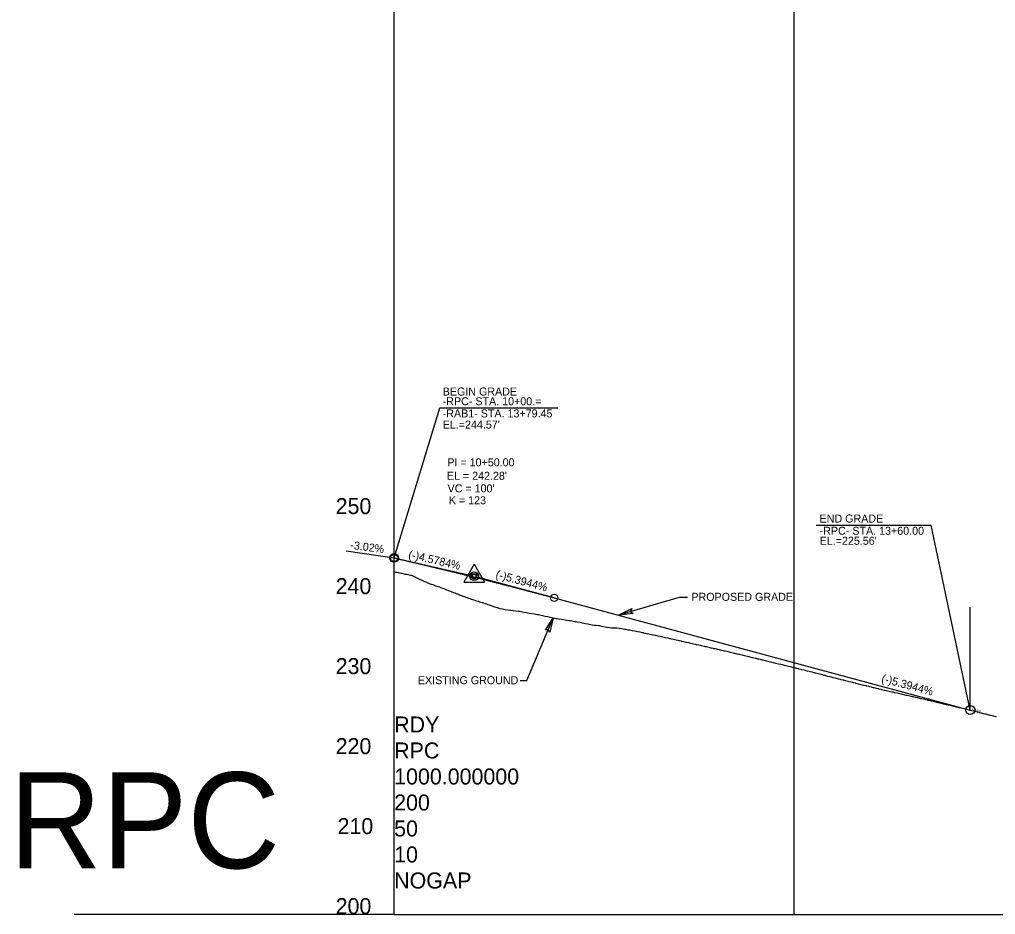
# Model space of a CAD drawing. Extents: x 2115752 to 2121174, y 562881 to 567245.
# Drawn here: x 2116462 to 2117072, y 563768 to 564327 of the extents above; entities that cross this region are included whole.
import ezdxf

# ---------------------------------------------------------------- set-up
doc = ezdxf.new("R2010")
doc.units = 0
for name, color, linetype in [('Exist Profile Cell', 7, 'Continuous'), ('Exist Vertical Profile Ground Line', 7, 'Continuous'), ('Exist Vertical Profile Vertical Axis Label', 7, 'Continuous'), ('Prop PFL VPI Symbol CELL', 7, 'Continuous'), ('Prop Terminator CELL', 7, 'Continuous'), ('Prop Vertical Profile Curve Label', 7, 'Continuous'), ('Prop Vertical Profile Grade', 7, 'Continuous'), ('Prop Vertical Profile Grade Label', 7, 'Continuous'), ('Prop VPI Label', 7, 'Continuous'), ('Scratch_Level_1', 7, 'Continuous')]:
    doc.layers.add(name, color=color, linetype=linetype)

msp = doc.modelspace()

# ---------------------------------------------------------------- linework, layer by layer
at = {"layer": 'Exist Profile Cell'}
for q in [(2116696.3, 564017.63), (2117393.32, 563767.63), (2116696.3, 563767.63)]:
    msp.add_line((2116696.3, 563767.63), q, dxfattribs=at)
at = {"layer": 'Exist Vertical Profile Ground Line'}
msp.add_lwpolyline([(2116696.3, 563981.85), (2116697.16, 563981.66), (2116698.02, 563981.48), (2116698.89, 563981.29), (2116699.74, 563981.13), (2116700.67, 563980.95), (2116701.01, 563980.87), (2116701.69, 563980.75), (2116702.32, 563980.61), (2116703.24, 563980.42), (2116704.13, 563980.28), (2116704.9, 563980.14), (2116705.76, 563979.97), (2116706.62, 563979.81), (2116706.94, 563979.75), (2116707.48, 563979.52), (2116708.34, 563979.15), (2116709.25, 563978.76), (2116710.06, 563978.34), (2116710.92, 563977.89), (2116711.78, 563977.44), (2116712.64, 563977), (2116713.11, 563976.76), (2116713.5, 563976.58), (2116714.36, 563976.2), (2116715.22, 563975.82), (2116716.08, 563975.44), (2116716.94, 563975.06), (2116717.8, 563974.69), (2116718.16, 563974.53), (2116718.67, 563974.37), (2116719.53, 563974.09), (2116720.39, 563973.8), (2116721.25, 563973.44), (2116722.11, 563973.08), (2116722.97, 563972.76), (2116723.83, 563972.57), (2116724.71, 563972.37), (2116725.55, 563972.02), (2116726.41, 563971.66), (2116727.27, 563971.31), (2116728.13, 563970.96), (2116728.99, 563970.62), (2116729.85, 563970.28), (2116730.71, 563969.94), (2116731.57, 563969.61), (2116732.43, 563969.28), (2116733.29, 563968.96), (2116734.15, 563968.64), (2116735.01, 563968.32), (2116735.53, 563968.13), (2116735.87, 563967.96), (2116736.73, 563967.55), (2116737.59, 563967.23), (2116738.45, 563966.92), (2116739.31, 563966.6), (2116740.17, 563966.29), (2116741.03, 563965.99), (2116741.89, 563965.68), (2116742.75, 563965.38), (2116743.61, 563965.09), (2116744.47, 563964.79), (2116745.33, 563964.5), (2116746.19, 563964.22), (2116747.05, 563963.93), (2116747.91, 563963.65), (2116748.77, 563963.38), (2116749.73, 563963.07), (2116750.49, 563962.87), (2116751.35, 563962.66), (2116751.78, 563962.55), (2116752.21, 563962.39), (2116753.07, 563962.07), (2116753.93, 563961.75), (2116754.79, 563961.44), (2116755.65, 563961.14), (2116757.32, 563960.56), (2116758.98, 563959.98), (2116760.65, 563959.41), (2116762.39, 563958.83), (2116763.99, 563958.58), (2116765.66, 563958.34), (2116767.33, 563958.1), (2116768.51, 563957.93), (2116768.99, 563957.86), (2116770.66, 563957.63), (2116772.33, 563957.4), (2116774, 563957.18), (2116774.62, 563957.11), (2116775.67, 563956.91), (2116777.34, 563956.61), (2116779, 563956.31), (2116780.67, 563956.03), (2116782.34, 563955.74), (2116784.01, 563955.47), (2116785.68, 563955.2), (2116786.56, 563955.05), (2116787.35, 563954.88), (2116789.01, 563954.51), (2116790.68, 563954.15), (2116792.35, 563953.79), (2116794.02, 563953.43), (2116795.69, 563953.07), (2116797.36, 563952.72), (2116798.25, 563952.53), (2116799.02, 563952.42), (2116800.69, 563952.18), (2116802.36, 563951.92), (2116804.03, 563951.66), (2116805.7, 563951.4), (2116806.22, 563951.32), (2116807.37, 563951.12), (2116809.03, 563950.83), (2116809.73, 563950.71), (2116810.7, 563950.54), (2116812.37, 563950.25), (2116814.04, 563949.95), (2116815.71, 563949.6), (2116817.38, 563949.26), (2116819.04, 563948.92), (2116821, 563948.52), (2116822.49, 563948.47), (2116824.05, 563948.24), (2116824.61, 563948.16), (2116825.72, 563947.92), (2116827.39, 563947.56), (2116828.12, 563947.4), (2116828.98, 563947.24), (2116830.81, 563946.91), (2116832.18, 563946.86), (2116833.78, 563946.86), (2116834.97, 563946.86), (2116835.38, 563946.8), (2116836.98, 563946.54), (2116838.58, 563946.27), (2116840.17, 563946.01), (2116840.83, 563945.9), (2116841.77, 563945.73), (2116842.47, 563945.6), (2116843.37, 563945.45), (2116844.97, 563945.18), (2116846.48, 563944.93), (2116847.46, 563944.72), (2116848.37, 563944.53), (2116849.82, 563944.22), (2116851.37, 563943.88), (2116851.84, 563943.77), (2116852.19, 563943.7), (2116852.96, 563943.53), (2116853.39, 563943.44), (2116854.25, 563943.25), (2116854.67, 563943.17), (2116856.22, 563942.87), (2116857.84, 563942.51), (2116858.36, 563942.4), (2116859.36, 563942.19), (2116859.7, 563942.12), (2116860.41, 563941.96), (2116860.96, 563941.85), (2116862.56, 563941.49), (2116863.34, 563941.32), (2116864.15, 563941.15), (2116865.87, 563940.79), (2116867.35, 563940.46), (2116868.42, 563940.22), (2116868.95, 563940.1), (2116869.69, 563939.93), (2116870.76, 563939.69), (2116872.44, 563939.31), (2116873.75, 563939.01), (2116875.34, 563938.65), (2116875.91, 563938.52), (2116877.03, 563938.27), (2116877.96, 563938.06), (2116878.54, 563937.92), (2116880.14, 563937.56), (2116880.92, 563937.39), (2116881.74, 563937.2), (2116883.34, 563936.83), (2116884.33, 563936.6), (2116884.94, 563936.47), (2116885.74, 563936.29), (2116886.62, 563936.1), (2116887.45, 563935.9), (2116888.13, 563935.74), (2116890.03, 563935.31), (2116890.49, 563935.21), (2116891.33, 563935.02), (2116892.15, 563934.83), (2116892.93, 563934.66), (2116893.64, 563934.5), (2116894.19, 563934.38), (2116894.53, 563934.3), (2116895.74, 563934.03), (2116896.13, 563933.94), (2116896.79, 563933.79), (2116897.73, 563933.58), (2116898.34, 563933.44), (2116899.32, 563933.22), (2116899.94, 563933.08), (2116900.96, 563932.84), (2116902.8, 563932.43), (2116903.14, 563932.35), (2116904.12, 563932.12), (2116905.72, 563931.75), (2116906.5, 563931.57), (2116907.32, 563931.38), (2116908.92, 563931), (2116909.58, 563930.84), (2116909.89, 563930.77), (2116910.52, 563930.62), (2116911.71, 563930.32), (2116912.11, 563930.23), (2116912.85, 563930.05), (2116913.71, 563929.84), (2116914.1, 563929.75), (2116915.31, 563929.45), (2116916.15, 563929.25), (2116917, 563929.04), (2116917.96, 563928.81), (2116918.52, 563928.68), (2116919.46, 563928.44), (2116920.14, 563928.28), (2116921.8, 563927.89), (2116922.32, 563927.76), (2116922.82, 563927.64), (2116923.36, 563927.51), (2116924.07, 563927.34), (2116924.98, 563927.13), (2116925.41, 563927.02), (2116925.83, 563926.92), (2116926.2, 563926.83), (2116926.59, 563926.74), (2116928.2, 563926.34), (2116929.05, 563926.13), (2116929.82, 563925.95), (2116931.43, 563925.56), (2116933.06, 563925.15), (2116934.66, 563924.76), (2116936.54, 563924.3), (2116937.89, 563923.98), (2116939.5, 563923.58), (2116940.06, 563923.44), (2116941.11, 563923.19), (2116942.73, 563922.81), (2116943.68, 563922.58), (2116944.34, 563922.42), (2116945.95, 563922.04), (2116946.87, 563921.82), (2116947.23, 563921.73), (2116947.57, 563921.65), (2116948.83, 563921.35), (2116949.18, 563921.26), (2116950.39, 563920.95), (2116950.86, 563920.83), (2116952.41, 563920.46), (2116954.13, 563920), (2116954.54, 563919.9), (2116955.63, 563919.62), (2116957.25, 563919.2), (2116958.29, 563918.93), (2116958.86, 563918.78), (2116959.45, 563918.63), (2116960.48, 563918.37), (2116962.09, 563917.96), (2116962.98, 563917.73), (2116963.82, 563917.52), (2116964.77, 563917.27), (2116965.31, 563917.13), (2116965.88, 563916.98), (2116967.09, 563916.68), (2116968.54, 563916.31), (2116969.79, 563915.98), (2116970.34, 563915.85), (2116971.87, 563915.46), (2116973.74, 563915.01), (2116974.99, 563914.71), (2116975.44, 563914.6), (2116976.8, 563914.25), (2116977.21, 563914.14), (2116977.72, 563914.01), (2116978.22, 563913.89), (2116979.98, 563913.44), (2116981.69, 563913.01), (2116982.51, 563912.8), (2116983.14, 563912.64), (2116984.3, 563912.34), (2116984.68, 563912.25), (2116986.3, 563911.85), (2116987.91, 563911.45), (2116989.52, 563911.05), (2116990.09, 563910.91), (2116991.13, 563910.65), (2116991.46, 563910.57), (2116992.74, 563910.25), (2116993.26, 563910.12), (2116994.36, 563909.84), (2116995.56, 563909.54), (2116995.97, 563909.45), (2116996.83, 563909.24), (2116997.58, 563909.06), (2116998.66, 563908.8), (2116999.2, 563908.68), (2117000.44, 563908.37), (2117000.81, 563908.29), (2117001.67, 563908.1), (2117002.42, 563907.93), (2117003.1, 563907.77), (2117004.04, 563907.55), (2117004.68, 563907.41), (2117005.65, 563907.19), (2117007.26, 563906.84), (2117007.8, 563906.72), (2117008.88, 563906.47), (2117010.65, 563906.07), (2117011.25, 563905.93), (2117012.2, 563905.72), (2117013.07, 563905.52), (2117013.72, 563905.37), (2117014.88, 563905.11), (2117015.33, 563905.01), (2117016.95, 563904.64), (2117018.56, 563904.27), (2117019.49, 563904.05), (2117020.33, 563903.85), (2117021.78, 563903.52), (2117022.4, 563903.37), (2117023.4, 563903.15), (2117023.98, 563903.01), (2117025.29, 563902.71), (2117026.72, 563902.38), (2117027.64, 563902.16), (2117028.24, 563902.02), (2117029.48, 563901.73), (2117029.85, 563901.65), (2117031.05, 563901.37), (2117031.47, 563901.27), (2117031.81, 563901.19), (2117033.16, 563900.86), (2117033.91, 563900.69), (2117034.69, 563900.5), (2117035, 563900.43), (2117036.31, 563900.12), (2117037.03, 563899.95), (2117037.92, 563899.74), (2117039.59, 563899.34), (2117041.15, 563898.97), (2117042.43, 563898.67), (2117042.76, 563898.59), (2117044.37, 563898.23), (2117045.2, 563898.04), (2117045.99, 563897.86), (2117047.6, 563897.48), (2117048, 563897.39), (2117049.21, 563897.1), (2117050.83, 563896.71), (2117051.73, 563896.5), (2117052.44, 563896.33), (2117053.75, 563896.02), (2117054.05, 563895.95), (2117055.67, 563895.57), (2117056.29, 563895.43), (2117057.28, 563895.18), (2117058.49, 563894.89), (2117059.27, 563894.7), (2117059.75, 563894.57), (2117060.51, 563894.38), (2117061.14, 563894.21), (2117061.77, 563894.04), (2117062.12, 563893.96), (2117063.06, 563893.72), (2117063.73, 563893.54), (2117064.53, 563893.34), (2117065.35, 563893.14), (2117066, 563892.98), (2117067.22, 563892.67), (2117068.13, 563892.44), (2117068.76, 563892.29), (2117069.95, 563891.99), (2117070.69, 563891.8), (2117071.45, 563891.6), (2117072.65, 563891.3)], dxfattribs=at)
at = {"layer": 'Prop PFL VPI Symbol CELL'}
for p, q in [((2116746.3, 563986.52), (2116739.85, 563975.32)), ((2116746.3, 563986.52), (2116752.8, 563975.32)), ((2116739.85, 563975.32), (2116752.8, 563975.32))]:
    msp.add_line(p, q, dxfattribs=at)
for radius in [1.75, 1.2]:
    msp.add_circle((2116746.3, 563979.03), radius, dxfattribs=at)
at = {"layer": 'Prop Terminator CELL'}
for points in [[(2116845.56, 563955.75), (2116836.49, 563954.71), (2116844.72, 563958.79), (2116844.07, 563956.93)], [(2116790.78, 563945.37), (2116795.69, 563953.07), (2116793.66, 563944.11), (2116792.63, 563945.79)]]:
    msp.add_lwpolyline(points, close=True, dxfattribs=at)
at = {"layer": 'Prop Vertical Profile Curve Label'}
for centre in [(2116696.3, 563990.48), (2116796.3, 563965.55)]:
    msp.add_circle(centre, 2.25, dxfattribs=at)
at = {"layer": 'Prop Vertical Profile Grade'}
msp.add_line((2116796.3, 563965.55), (2117056.3, 563895.42), dxfattribs=at)
msp.add_spline([(2116696.3, 563990.48), (2116698.3, 563990.02), (2116700.3, 563989.56), (2116702.3, 563989.1), (2116704.3, 563988.64), (2116706.3, 563988.17), (2116708.3, 563987.7), (2116710.3, 563987.24), (2116712.3, 563986.76), (2116714.3, 563986.29), (2116716.3, 563985.82), (2116718.3, 563985.34), (2116720.3, 563984.87), (2116722.3, 563984.39), (2116724.3, 563983.91), (2116726.3, 563983.43), (2116728.3, 563982.95), (2116730.3, 563982.46), (2116732.3, 563981.97), (2116734.3, 563981.49), (2116736.3, 563981), (2116738.3, 563980.51), (2116740.3, 563980.01), (2116742.3, 563979.52), (2116744.3, 563979.02), (2116746.3, 563978.52), (2116748.3, 563978.02), (2116750.3, 563977.52), (2116752.3, 563977.02), (2116754.3, 563976.52), (2116756.3, 563976.01), (2116758.3, 563975.5), (2116760.3, 563974.99), (2116762.3, 563974.48), (2116764.3, 563973.97), (2116766.3, 563973.46), (2116768.3, 563972.94), (2116770.3, 563972.42), (2116772.3, 563971.9), (2116774.3, 563971.38), (2116776.3, 563970.86), (2116778.3, 563970.34), (2116780.3, 563969.81), (2116782.3, 563969.28), (2116784.3, 563968.76), (2116786.3, 563968.22), (2116788.3, 563967.69), (2116790.3, 563967.16), (2116792.3, 563966.62), (2116794.3, 563966.09), (2116796.3, 563965.55)], degree=3, dxfattribs=at)
at = {"layer": 'Prop VPI Label'}
for p, q in [((2116696.3, 563990.48), (2116724.86, 564084.29)), ((2116724.86, 564084.29), (2116798.55, 564084.29)), ((2116959.9, 564010.91), (2117031.83, 564010.91)), ((2117056.3, 563895.42), (2117031.83, 564010.91)), ((2116666.3, 563994.98), (2116696.3, 563990.48)), ((2116696.3, 563990.48), (2116743.62, 563979.65)), ((2116796.3, 563965.55), (2116748.96, 563978.32))]:
    msp.add_line(p, q, dxfattribs=at)
for points in [[(2116879.6, 563965.77), (2116874.3, 563965.77), (2116836.49, 563954.71)], [(2116775, 563913.81), (2116779.22, 563913.81), (2116795.69, 563953.07)]]:
    msp.add_lwpolyline(points, dxfattribs=at)
for centre in [(2116696.3, 563990.48), (2116746.3, 563979.03), (2117056.3, 563895.42)]:
    msp.add_circle(centre, 2.75, dxfattribs=at)
at = {"layer": 'Scratch_Level_1'}
for p, q in [((2116946.3, 563767.63), (2116946.3, 564698.4)), ((2116696.3, 563767.63), (2116696.3, 564637.02)), ((2117056.3, 563895.42), (2117056.3, 563959.67)), ((2117016.3, 563904.78), (2117016.95, 563904.64)), ((2117016.95, 563904.64), (2117018.56, 563904.27)), ((2117018.56, 563904.27), (2117021.78, 563903.52)), ((2117023.98, 563903.01), (2117026.72, 563902.38)), ((2117028.24, 563902.02), (2117031.05, 563901.37)), ((2117036.3, 563900.12), (2117044.37, 563898.23)), ((2117046.3, 563897.78), (2117047.6, 563897.48)), ((2117056.3, 563895.42), (2117058.49, 563894.89)), ((2117056.3, 563895.42), (2117059.27, 563894.7)), ((2116696.3, 563767.63), (2116496.27, 563767.63))]:
    msp.add_line(p, q, dxfattribs=at)

# ---------------------------------------------------------------- texts
at = {"layer": 'Exist Profile Cell'}
for s, p in [('RDY', (2116696.3, 563881.38)), ('RPC', (2116696.3, 563865.13)), ('1000.000000', (2116696.3, 563848.88)), ('200', (2116696.3, 563832.63)), ('50', (2116696.3, 563816.38)), ('10', (2116696.3, 563800.13)), ('NOGAP', (2116696.3, 563783.88))]:
    msp.add_text(s, height=10, dxfattribs=at).set_placement(p)
at = {"layer": 'Exist Vertical Profile Vertical Axis Label'}
for s, height, p in [('250', 10, (2116659.74, 564017.88)), ('240', 10, (2116659.74, 563967.88)), ('230', 10, (2116659.74, 563917.88)), ('220', 10, (2116659.74, 563867.88)), ('RPC', 60, (2116455.62, 563796.52)), ('210', 10, (2116660.93, 563817.88)), ('200', 10, (2116659.74, 563767.88))]:
    msp.add_text(s, height=height, dxfattribs=at).set_placement(p)
at = {"layer": 'Prop Vertical Profile Curve Label'}
for s, p in [("VC = 100'", (2116729.67, 564031.45)), ('K = 123', (2116730.47, 564024.02))]:
    msp.add_text(s, height=5, dxfattribs=at).set_placement(p)
at = {"layer": 'Prop Vertical Profile Grade Label'}
for s, rotation, p in [('-3.02%', 352.40079, (2116668.68, 563996.23)), ('(-)4.5784%', 347.10602, (2116704.87, 563990.47)), ('(-)5.3944%', 344.90539, (2116759.36, 563978.04)), ('(-)5.3944%', 344.90539, (2117000.43, 563913.02))]:
    msp.add_text(s, height=5, rotation=rotation, dxfattribs=at).set_placement(p)
at = {"layer": 'Prop VPI Label'}
for s, p in [('BEGIN GRADE', (2116726.63, 564091.99)), ('-RPC- STA. 10+00.=', (2116726.63, 564085.89)), ('-RAB1- STA. 13+79.45', (2116726.63, 564078.31)), ("EL.=244.57'", (2116726.63, 564071.31)), ('PI = 10+50.00', (2116729.53, 564047.73)), ("EL = 242.28'", (2116729.23, 564039.33)), ('END GRADE', (2116962.13, 564012.6)), ('-RPC- STA. 13+60.00', (2116962.17, 564004.96)), ("EL.=225.56'", (2116962.17, 563998.71)), ('PROPOSED GRADE', (2116882.02, 563963.67)), ('EXISTING GROUND', (2116711.12, 563911.57))]:
    msp.add_text(s, height=5, dxfattribs=at).set_placement(p)
at = {"layer": 'Scratch_Level_1'}
msp.add_text('-4.8946 %', height=1, rotation=346.24824, dxfattribs=at).set_placement((2117056.75, 563895.7))

doc.saveas('drawing.dxf')
